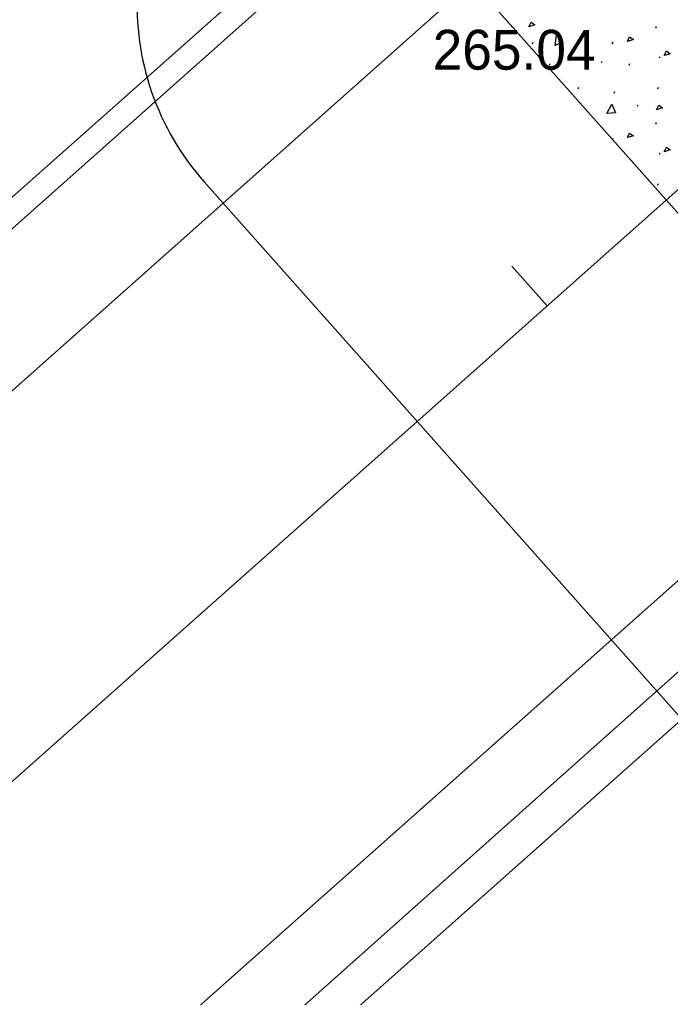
# Model space of a CAD drawing. Extents: x 49683 to 58852, y 49525 to 54803.
# Drawn here: x 53875.1 to 53924.1, y 51788.8 to 51862.4 of the extents above; entities that cross this region are included whole.
import ezdxf

# ---------------------------------------------------------------- set-up
doc = ezdxf.new("R2010")
doc.units = 0
for name, color, linetype in [('Level 11', 7, 'Continuous'), ('Level 13', 7, 'Continuous'), ('Level 15', 7, 'Continuous'), ('Level 18', 7, 'Continuous'), ('Level 19', 7, 'Continuous'), ('Level 3', 7, 'Continuous'), ('Level 32', 7, 'Continuous'), ('Level 5', 7, 'Continuous')]:
    doc.layers.add(name, color=color, linetype=linetype)

msp = doc.modelspace()

# ---------------------------------------------------------------- linework, layer by layer
at = {"layer": 'Level 11'}
msp.add_line((53245.856, 51207.553), (53944.235, 51830.768), dxfattribs=at)
at = {"layer": 'Level 13'}
msp.add_line((53681.554, 51593.39), (53996.93, 51873.722), dxfattribs=at)
at = {"layer": 'Level 15'}
for p, q in [((53460.734, 51466.679), (53909.18, 51865.296)), ((53938.412, 51832.41), (53909.18, 51865.296)), ((53923.006, 51861.928), (53923.02, 51861.803)), ((53917.622, 51861.192), (53917.677, 51861.317)), ((53913.731, 51860.623), (53913.786, 51860.748)), ((53919.731, 51860.623), (53919.786, 51860.748)), ((53917.263, 51859.638), (53917.318, 51859.555)), ((53923.263, 51859.638), (53923.318, 51859.555)), ((53914.993, 51859.013), (53915.049, 51859.138)), ((53918.882, 51859.285), (53918.937, 51859.202)), ((53920.993, 51859.013), (53921.049, 51859.138)), ((53917.158, 51857.223), (53917.213, 51857.348)), ((53919.869, 51856.904), (53919.925, 51857.029)), ((53923.158, 51857.223), (53923.213, 51857.348)), ((53921.604, 51856.016), (53921.659, 51855.933)), ((53923.006, 51854.685), (53923.02, 51854.56)), ((53919.745, 51853.412), (53919.786, 51853.505)), ((53923.263, 51852.395), (53923.318, 51852.312)), ((53923.158, 51849.981), (53923.213, 51850.106)), ((53938.412, 51832.41), (53489.966, 51433.793))]:
    msp.add_line(p, q, dxfattribs=at)
for points in [[(53913.456, 51861.906), (53913.622, 51862.253), (53913.9, 51862.045), (53913.456, 51861.906)], [(53915.419, 51860.479), (53915.529, 51861.272), (53916.026, 51860.759), (53915.432, 51860.484)], [(53920.874, 51860.793), (53921.04, 51861.14), (53921.318, 51860.932), (53920.874, 51860.793)], [(53923.649, 51859.735), (53923.816, 51860.082), (53924.093, 51859.873), (53923.649, 51859.735)], [(53919.318, 51855.366), (53919.692, 51856.073), (53919.984, 51855.421), (53919.331, 51855.366)], [(53923.061, 51855.656), (53923.227, 51856.003), (53923.505, 51855.794), (53923.061, 51855.656)], [(53920.874, 51853.55), (53921.04, 51853.897), (53921.318, 51853.689), (53920.874, 51853.55)], [(53923.649, 51852.492), (53923.816, 51852.839), (53924.093, 51852.631), (53923.649, 51852.492)]]:
    msp.add_lwpolyline(points, dxfattribs=at)
at = {"layer": 'Level 18'}
msp.add_line((53927.062, 51807.399), (53889.003, 51850.215), dxfattribs=at)
msp.add_arc((53903.952, 51863.502), 20, 131.2163, 221.63337, dxfattribs=at)
at = {"layer": 'Level 19'}
for p, q in [((52714.154, 50773.623), (54181.768, 52078.16)), ((53914.827, 51840.881), (53912.17, 51843.871))]:
    msp.add_line(p, q, dxfattribs=at)
at = {"layer": 'Level 3'}
msp.add_line((53449.718, 51471.806), (53898.742, 51870.567), dxfattribs=at)
at = {"layer": 'Level 5'}
msp.add_line((53900.074, 51869.402), (53451.19, 51470.163), dxfattribs=at)

# ---------------------------------------------------------------- texts
at = {"layer": 'Level 32'}
msp.add_text('265.04', height=3, dxfattribs=at).set_placement((53906.204, 51858.669))

doc.saveas('drawing.dxf')
